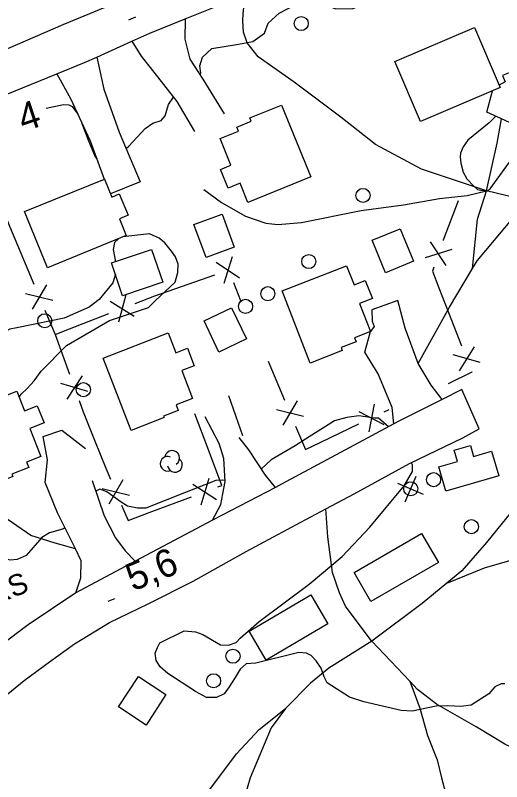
# Model space of a CAD drawing. Extents: x 362852 to 366875, y 5563573 to 5566479.
# Drawn here: x 363874.5 to 363943.6, y 5564816.7 to 5564925.6 of the extents above; entities that cross this region are included whole.
import ezdxf

# ---------------------------------------------------------------- set-up
doc = ezdxf.new("R2010")
doc.units = 0
for name, color, linetype in [('Niveau 19', 7, 'Continuous'), ('Niveau 2', 7, 'Continuous'), ('Niveau 21', 7, 'Continuous'), ('Niveau 22', 7, 'Continuous'), ('Niveau 3', 7, 'Continuous'), ('Niveau 31', 7, 'Continuous'), ('Niveau 36', 7, 'Continuous'), ('Niveau 37', 7, 'Continuous'), ('Niveau 44', 7, 'Continuous')]:
    doc.layers.add(name, color=color, linetype=linetype)

msp = doc.modelspace()

# ---------------------------------------------------------------- linework, layer by layer
at = {"layer": 'Niveau 19'}
for points in [[(363898.61, 5564925.08), (363898.55, 5564922.2), (363899.26, 5564919.35), (363901.09, 5564916.52), (363904.15, 5564911.57)], [(363952.27, 5564924.2), (363949.54, 5564920.62), (363945.08, 5564917.59), (363943.65, 5564917.03), (363944.03, 5564916.14), (363943.2, 5564915.67)], [(363891.04, 5564921.91), (363892.36, 5564919.76), (363893.64, 5564918.17), (363897.41, 5564913.32), (363899.92, 5564909.07)], [(363886.03, 5564919.65), (363887.04, 5564915.09), (363889.22, 5564908.99), (363892.22, 5564901.9), (363887.99, 5564900.23)], [(363880.36, 5564917.27), (363882.29, 5564913.77), (363885.12, 5564907.73), (363887.07, 5564902.29)], [(363956.14, 5564915.05), (363953.11, 5564914.84), (363951.63, 5564914.73), (363948.35, 5564913.76), (363945.91, 5564913.02), (363944.66, 5564910.37), (363943.52, 5564910.89), (363941.43, 5564911.83), (363942.25, 5564914.85)], [(363935.1, 5564870.99), (363933.55, 5564873), (363931.71, 5564876.09), (363929.84, 5564881.11), (363928.79, 5564885.05), (363925.1, 5564883.72), (363925.18, 5564882.12), (363925.43, 5564881.35), (363924.91, 5564880.63)], [(363928.23, 5564867.51), (363927.99, 5564869.84), (363926.01, 5564874.62), (363924.12, 5564877.69), (363924.91, 5564880.63)], [(363902.47, 5564853.86), (363903.65, 5564856.04), (363903.94, 5564857.6), (363904.27, 5564859.33), (363904.09, 5564862.59), (363903.45, 5564864.75), (363901.45, 5564868.53)], [(363883.09, 5564843.49), (363883.78, 5564845.66), (363883.85, 5564848.04), (363883, 5564849.75), (363880.45, 5564854.89), (363878.72, 5564859.2), (363879.05, 5564862.4), (363878.45, 5564865.73), (363881.08, 5564866.62), (363884.46, 5564864.04)], [(363911.42, 5564858.48), (363910, 5564860.24), (363907.62, 5564863.84), (363906.27, 5564865.58)], [(363885.38, 5564859.49), (363887.07, 5564854.46), (363888.68, 5564851.33), (363890.07, 5564849.48), (363891.48, 5564848)]]:
    msp.add_lwpolyline(points, dxfattribs=at)
at = {"layer": 'Niveau 2'}
for points in [[(363900.65, 5564917.2), (363900.82, 5564917.35), (363900.69, 5564918.42), (363901.07, 5564919.63), (363902.37, 5564920.86), (363906.17, 5564921.48), (363908.19, 5564921.87), (363909.88, 5564923.06), (363910.38, 5564924.45), (363911.96, 5564925.91), (363915.3, 5564927.65), (363916.71, 5564927.86), (363918.29, 5564927.19), (363919.95, 5564926.5), (363922.41, 5564926.57), (363924.73, 5564927.46), (363927.3, 5564928.95), (363931.28, 5564931.08), (363934.02, 5564932.77), (363935.99, 5564933.76), (363937.41, 5564933.78), (363939.68, 5564932.87)], [(363890.21, 5564906.64), (363890.59, 5564906.98), (363892.93, 5564909.5), (363893.99, 5564910.24), (363895.21, 5564910.62), (363895.75, 5564911.28), (363896.21, 5564912.9), (363896.92, 5564913.95)], [(363878.87, 5564912.39), (363881.32, 5564912.91), (363882.09, 5564912.86), (363882.56, 5564912.61), (363883.34, 5564911.53)], [(363942.73, 5564911.25), (363941.77, 5564910.32), (363938.74, 5564907.83), (363938.07, 5564906.87), (363937.69, 5564905.97), (363937.65, 5564905.45), (363937.77, 5564904.56), (363938.11, 5564903.27)], [(363883.88, 5564910.37), (363884.86, 5564907.75), (363885.8, 5564905.45), (363886.03, 5564905.2)], [(363938.11, 5564903.27), (363938.61, 5564902.35), (363939.49, 5564901.4), (363940.1, 5564900.84), (363940.58, 5564900.72), (363941.48, 5564900.66), (363941.94, 5564900.91), (363945.26, 5564905.58), (363945.71, 5564906.01), (363946.33, 5564906.33), (363947.2, 5564906.18), (363947.75, 5564905.6), (363948.25, 5564904.37), (363948.91, 5564902.89), (363949.8, 5564902.25), (363951.29, 5564901.8), (363955.09, 5564901.49), (363956.39, 5564900.59), (363956.99, 5564899.59), (363957.27, 5564898.27), (363959.82, 5564891.57), (363960.39, 5564889.6)], [(363875.03, 5564871.32), (363875.3, 5564871.73), (363876.14, 5564872.57), (363877.13, 5564873.66), (363878.13, 5564875.01), (363881.75, 5564878.67), (363887.83, 5564882.23), (363893.37, 5564884.06), (363894.4, 5564885.05), (363897.19, 5564887.68), (363897.57, 5564889.03), (363897.59, 5564890.22), (363897.23, 5564891.26), (363896.64, 5564892.08), (363895.72, 5564893.26), (363894.89, 5564893.92), (363893.52, 5564894.54), (363889.76, 5564894.08)], [(363889.13, 5564893.82), (363888.54, 5564893.31)], [(363888.54, 5564893.31), (363888.39, 5564892.31), (363888.68, 5564890.57)], [(363888.68, 5564888.79), (363888.34, 5564887.55), (363886.37, 5564885.19), (363884.95, 5564884.1), (363881.42, 5564882.53), (363874.69, 5564881.15), (363873.7, 5564880.99), (363872.97, 5564880.63), (363872.25, 5564879.65), (363869.62, 5564876.95), (363868.61, 5564876.53), (363867.67, 5564876.52), (363867.21, 5564876.64)], [(363927.5, 5564867.12), (363926.07, 5564868.33), (363925.51, 5564868.35), (363923.26, 5564868.67), (363921.56, 5564868.41), (363919.81, 5564867.95), (363915.71, 5564865.33), (363914.22, 5564864.41), (363910.81, 5564862.39), (363909.43, 5564861.11)], [(363881.5, 5564852.77), (363881.3, 5564852.6), (363880.19, 5564852.27), (363879.35, 5564852.05), (363878.26, 5564851.36), (363876, 5564848.81), (363874.74, 5564848.23), (363873.73, 5564848.13), (363869.31, 5564849.19), (363867.7, 5564850.08), (363866.61, 5564851.07), (363864.88, 5564854.23), (363863.96, 5564856.04), (363863.49, 5564857.34), (363863.03, 5564859.21), (363862.53, 5564861.81), (363863.09, 5564862.73), (363864.31, 5564863.1), (363867.59, 5564863.6)], [(363918.75, 5564830.72), (363918.35, 5564831.56), (363917.9, 5564832.81), (363917.23, 5564833.84), (363916.49, 5564834.6), (363915.84, 5564834.96), (363914.76, 5564835.01), (363908.65, 5564833.51), (363907.25, 5564833.43), (363906.39, 5564832.64), (363905.68, 5564831.48), (363904.86, 5564830.14), (363904.14, 5564829.16), (363903.04, 5564828.65), (363901.61, 5564828.63), (363900.08, 5564829.49), (363896.16, 5564832.07), (363895.04, 5564832.98), (363894.49, 5564833.88), (363894.36, 5564834.95), (363894.66, 5564835.75), (363895.02, 5564836.4), (363898.48, 5564838.13), (363900.05, 5564837.96), (363901.13, 5564837.59), (363903.6, 5564836.11), (363904.74, 5564836.08), (363905.83, 5564836.46), (363906.39, 5564837.07), (363909.1, 5564839.42), (363916.2, 5564844.76), (363920.89, 5564848.68), (363924.85, 5564852.86), (363929.69, 5564858.71), (363930.9, 5564860.77), (363930.9, 5564861.7), (363930.73, 5564861.99)], [(363904.26, 5564859.46), (363903.95, 5564859.51), (363902.97, 5564859.49), (363898.52, 5564857.72), (363893, 5564855.53), (363891.81, 5564855.54), (363890.39, 5564855.83), (363889.53, 5564856.41), (363887.49, 5564857.88), (363886.48, 5564858.22), (363885.89, 5564857.98)], [(363944.02, 5564830.6), (363943.47, 5564830.57), (363942.58, 5564830.14), (363941.74, 5564829.17), (363939.21, 5564827.57), (363937.75, 5564827.35), (363935.9, 5564827.46), (363934.24, 5564827.41), (363930.85, 5564826.7), (363929.26, 5564826.8), (363923.97, 5564828), (363921.96, 5564828.67), (363918.75, 5564830.72)]]:
    msp.add_lwpolyline(points, dxfattribs=at)
at = {"layer": 'Niveau 21'}
for points in [[(363870.87, 5564919.76), (363881.25, 5564924.26), (363891.6, 5564928.59), (363895.41, 5564930.17), (363900.53, 5564932.29), (363912.57, 5564937.29), (363928.35, 5564943.82), (363934.53, 5564946.23), (363937.14, 5564949.17), (363938.65, 5564952.79), (363938.85, 5564955.05), (363937.93, 5564957.54), (363937.26, 5564959.37), (363935.43, 5564963.45), (363931.81, 5564971.51), (363925.69, 5564985.72), (363924.02, 5564989.86), (363921.9, 5564995.12), (363920.66, 5564998.21), (363916.03, 5565008.95), (363915.68, 5565009.77), (363911.22, 5565019.68)], [(363873.15, 5564914.32), (363880.36, 5564917.27), (363884.3, 5564918.87), (363886.03, 5564919.65), (363891.04, 5564921.91), (363893.56, 5564923.05), (363898.61, 5564925.08), (363903.57, 5564927.08)], [(363870.3, 5564826.66), (363875.72, 5564831.07), (363879.31, 5564833.72), (363882.86, 5564836.28), (363887.87, 5564839.29), (363893.32, 5564841.94), (363899.72, 5564845.19), (363907.27, 5564849.39), (363915.03, 5564853.57), (363918.57, 5564855.45), (363922.59, 5564857.59), (363930.48, 5564861.87), (363938.02, 5564865.52), (363940.34, 5564866.84), (363939.31, 5564869.19), (363937.89, 5564872.39), (363935.1, 5564870.99), (363929.05, 5564867.96), (363928.23, 5564867.51), (363921.29, 5564863.78), (363912.28, 5564858.93), (363911.42, 5564858.48), (363902.47, 5564853.86), (363891.48, 5564848), (363883.09, 5564843.49), (363876.29, 5564838.96), (363872.44, 5564836.06)]]:
    msp.add_lwpolyline(points, dxfattribs=at)
at = {"layer": 'Niveau 22'}
for points in [[(363947.47, 5564899.17), (363941.42, 5564900.62), (363932.16, 5564903.74), (363925.62, 5564907.21), (363920.71, 5564911.11), (363914.08, 5564916.09), (363908.95, 5564919.67), (363907.4, 5564921.67), (363906.9, 5564923.21), (363906.81, 5564924.8), (363906.84, 5564925.81), (363907.11, 5564928.49)], [(363931.71, 5564876.09), (363936.13, 5564884.11), (363939.43, 5564889.62), (363940.09, 5564890.71), (363945.22, 5564896.83), (363947.47, 5564899.17), (363949.77, 5564901.55), (363951.47, 5564904.87), (363952.44, 5564907.39), (363952.94, 5564910.8), (363953.11, 5564914.84)], [(363939.43, 5564889.62), (363940.13, 5564896.61), (363941.42, 5564900.62), (363942.9, 5564907.42), (363943.52, 5564910.89)], [(363901.24, 5564900.82), (363903.74, 5564898.99), (363907.17, 5564897.05), (363910.06, 5564896.05), (363911.76, 5564895.87), (363915.14, 5564896.13), (363923.58, 5564897.83), (363929.59, 5564898.65), (363934.74, 5564899.55), (363938.67, 5564899.97), (363941.42, 5564900.62)], [(363883, 5564849.75), (363880.14, 5564850.58), (363876.7, 5564851.65), (363868.05, 5564857.58), (363865.4, 5564859.18), (363859.06, 5564860.51), (363849.16, 5564863.16), (363839.58, 5564865.1), (363829.88, 5564868.57), (363813.72, 5564873.06), (363805.19, 5564874.87), (363802.57, 5564876.23), (363801.32, 5564877.47), (363800.22, 5564878.64), (363797.88, 5564883.08)], [(363955.07, 5564870.77), (363951.94, 5564867.1), (363948.66, 5564861.82), (363946.28, 5564856.69), (363941.4, 5564850.64), (363937.88, 5564846.65), (363935.77, 5564844.9), (363932.27, 5564842.01), (363925.13, 5564836.65), (363919.01, 5564832.81), (363916.4, 5564830.69), (363912.85, 5564827.07), (363910.81, 5564824.31), (363907.84, 5564817.22), (363907.15, 5564814.95), (363904.68, 5564808.83), (363904, 5564802.89), (363903.68, 5564795.78)], [(363925.13, 5564836.65), (363925.03, 5564836.75), (363921.37, 5564841.61), (363920.53, 5564843.51), (363919.54, 5564846.42), (363918.87, 5564851.46), (363918.57, 5564855.45)], [(363935.77, 5564844.9), (363941.14, 5564847.05), (363947.64, 5564848.97), (363950.18, 5564849.33), (363953.77, 5564849.68), (363955.45, 5564849.89), (363958.04, 5564850.04), (363961.76, 5564850.06)], [(363995.27, 5564797), (363989.87, 5564795.79), (363982.96, 5564796.39), (363980.69, 5564797.39), (363978.61, 5564799.08), (363972.92, 5564804.79), (363969.64, 5564807.5), (363963.29, 5564812.38), (363961.25, 5564813.45), (363959.64, 5564814.31), (363958.81, 5564814.74), (363953.41, 5564817.56), (363944, 5564822), (363939.92, 5564824.49), (363934.28, 5564827.71), (363931.61, 5564829.78), (363930.51, 5564830.95), (363925.13, 5564836.65)], [(363930.51, 5564830.95), (363931.91, 5564827.11), (363933.02, 5564823.23), (363934.38, 5564819.8), (363935.01, 5564817.2), (363936.28, 5564812.42), (363937.25, 5564808.75), (363939.12, 5564802.29), (363939.63, 5564800.51)], [(363890.05, 5564800.28), (363896.53, 5564808.36), (363901.23, 5564814.41), (363905.91, 5564820.63), (363909.09, 5564824.1), (363912.85, 5564827.07)]]:
    msp.add_lwpolyline(points, dxfattribs=at)
at = {"layer": 'Niveau 3'}
for p, q in [((363890.61, 5564924.96), (363891.59, 5564925.35)), ((363887.66, 5564842.32), (363888.62, 5564842.71))]:
    msp.add_line(p, q, dxfattribs=at)
at = {"layer": 'Niveau 31'}
for points in [[(363943.35, 5564915.32), (363941.68, 5564914.61), (363932.04, 5564910.49), (363928.4, 5564919.02), (363939.72, 5564923.84), (363943.35, 5564915.32)], [(363916.44, 5564902.64), (363907.5, 5564898.99), (363906.39, 5564901.71), (363904.69, 5564901.01), (363903.6, 5564903.67), (363905.09, 5564904.28), (363903.55, 5564908.07), (363906.16, 5564909.13), (363905.92, 5564909.7), (363907.99, 5564910.54), (363907.8, 5564910.99), (363912.29, 5564912.82), (363916.44, 5564902.64)], [(363875.77, 5564897.68), (363887.13, 5564902.32), (363888.18, 5564899.76), (363889.24, 5564900.19), (363890.48, 5564897.16), (363889.26, 5564896.66), (363890.23, 5564894.27), (363879.03, 5564889.7), (363875.77, 5564897.68)], [(363903.85, 5564897.32), (363905.57, 5564892.64), (363901.57, 5564891.17), (363899.85, 5564895.84), (363903.85, 5564897.32)], [(363927.06, 5564888.99), (363925.17, 5564893.62), (363929.16, 5564895.25), (363931.05, 5564890.62), (363927.06, 5564888.99)], [(363893.82, 5564892.32), (363895.41, 5564887.66), (363889.72, 5564885.73), (363888.14, 5564890.39), (363893.82, 5564892.32)], [(363912.38, 5564886.44), (363921.53, 5564890), (363922.59, 5564887.27), (363924.19, 5564887.89), (363925.19, 5564885.34), (363923.35, 5564884.63), (363924.91, 5564880.63), (363922.67, 5564879.76), (363922.89, 5564879.19), (363920.75, 5564878.36), (363920.92, 5564877.94), (363916.37, 5564876.17), (363912.38, 5564886.44)], [(363905.17, 5564884.02), (363907.29, 5564879.59), (363903.4, 5564877.73), (363901.28, 5564882.16), (363905.17, 5564884.02)], [(363886.95, 5564876.88), (363896.17, 5564880.47), (363897.28, 5564877.63), (363898.93, 5564878.27), (363899.9, 5564875.78), (363898.12, 5564875.09), (363899.66, 5564871.14), (363897.31, 5564870.23), (363897.62, 5564869.42), (363895.53, 5564868.61), (363895.61, 5564868.41), (363890.95, 5564866.59), (363886.95, 5564876.88)], [(363865.62, 5564868.59), (363874.69, 5564872.17), (363875.79, 5564869.39), (363877.58, 5564870.1), (363878.55, 5564867.66), (363876.54, 5564866.87), (363878.12, 5564862.89), (363876.07, 5564862.08), (363876.38, 5564861.32), (363873.99, 5564860.38), (363874.13, 5564860.03), (363869.7, 5564858.27), (363865.62, 5564868.59)], [(363943.15, 5564860.14), (363935.64, 5564857.97), (363934.65, 5564861.4), (363937.29, 5564862.17), (363936.83, 5564863.77), (363939.12, 5564864.43), (363939.57, 5564862.9), (363942.13, 5564863.64), (363943.15, 5564860.14)], [(363934.57, 5564847.82), (363924.98, 5564842.29), (363922.6, 5564846.41), (363932.19, 5564851.94), (363934.57, 5564847.82)], [(363918.88, 5564839.12), (363910.1, 5564833.95), (363907.69, 5564838.04), (363916.47, 5564843.22), (363918.88, 5564839.12)], [(363895.87, 5564829.06), (363893.04, 5564824.72), (363889.11, 5564827.29), (363891.95, 5564831.63), (363895.87, 5564829.06)]]:
    msp.add_lwpolyline(points, dxfattribs=at)
at = {"layer": 'Niveau 36'}
for p, q in [((363929.86, 5564856.44), (363931.41, 5564860.11)), ((363932.47, 5564857.5), (363928.8, 5564859.05))]:
    msp.add_line(p, q, dxfattribs=at)
for centre in [(363915.08, 5564924.41), (363923.86, 5564899.98), (363916.16, 5564890.59), (363910.34, 5564886.02), (363907.18, 5564884.22), (363878.65, 5564882.17), (363884.14, 5564872.38), (363933.89, 5564859.59), (363930.64, 5564858.3), (363939.25, 5564852.91), (363905.39, 5564834.5), (363902.64, 5564831.01)]:
    msp.add_circle(centre, 1, dxfattribs=at)
at = {"layer": 'Niveau 37'}
for p, q in [((363874.78, 5564892.91), (363877.1, 5564887.38)), ((363935.69, 5564890.05), (363933.46, 5564893.37)), ((363936.48, 5564892.32), (363932.67, 5564891.1)), ((363905.28, 5564891.28), (363904.08, 5564887.47)), ((363903.02, 5564890.48), (363906.34, 5564888.26)), ((363897.14, 5564886.72), (363902.8, 5564888.72)), ((363878.88, 5564887.27), (363876.86, 5564883.81)), ((363905.46, 5564887.63), (363906.48, 5564885.04)), ((363879.81, 5564885.05), (363875.93, 5564886.02)), ((363890.18, 5564885.84), (363889.11, 5564881.98)), ((363887.94, 5564884.97), (363891.34, 5564882.85)), ((363935.66, 5564884.22), (363937.86, 5564878.63)), ((363882.19, 5564881.02), (363887.78, 5564883.19)), ((363880.12, 5564880.21), (363882.18, 5564874.57)), ((363939.63, 5564878.48), (363937.53, 5564875.07)), ((363910.37, 5564876.42), (363912.71, 5564870.9)), ((363940.51, 5564876.25), (363936.65, 5564877.31)), ((363883.95, 5564874.37), (363881.77, 5564871.02)), ((363884.77, 5564872.12), (363880.94, 5564873.28)), ((363906.78, 5564865.84), (363904.81, 5564871.51)), ((363914.49, 5564870.79), (363912.48, 5564867.33)), ((363925.46, 5564870.34), (363924.67, 5564866.41)), ((363901.9, 5564863.82), (363899.95, 5564868.94)), ((363915.43, 5564868.58), (363911.55, 5564869.54)), ((363923.29, 5564869.3), (363926.84, 5564867.45)), ((363926.87, 5564869.24), (363927.56, 5564869.57)), ((363917.85, 5564864.93), (363923.26, 5564867.52)), ((363889.76, 5564859.56), (363887.76, 5564856.1)), ((363899.7, 5564858.95), (363903.06, 5564856.79)), ((363901.94, 5564859.78), (363900.81, 5564855.95)), ((363890.7, 5564857.35), (363886.82, 5564858.31)), ((363893.88, 5564855.08), (363899.51, 5564857.17))]:
    msp.add_line(p, q, dxfattribs=at)
for points in [[(363872.55, 5564898.48), (363873.64, 5564895.61), (363874.78, 5564892.91)], [(363937.37, 5564899.2), (363935.25, 5564893.63), (363935.24, 5564893.59)], [(363933.92, 5564889.81), (363933.71, 5564889.21), (363934.62, 5564886.85), (363935.66, 5564884.22)], [(363891.51, 5564884.64), (363894.31, 5564885.73), (363897.14, 5564886.72)], [(363878.65, 5564883.69), (363880.12, 5564880.21), (363882.19, 5564881.02)], [(363939.32, 5564874.91), (363939.33, 5564874.89), (363935.97, 5564873.21)], [(363883.55, 5564870.82), (363884.13, 5564869.22), (363885.72, 5564865.22)], [(363914.27, 5564867.21), (363915.68, 5564863.9), (363917.85, 5564864.93)], [(363885.72, 5564865.22), (363887.32, 5564861.22), (363887.98, 5564859.67)], [(363903.26, 5564858.57), (363903.82, 5564858.78), (363901.9, 5564863.82)], [(363889.55, 5564855.99), (363890.48, 5564853.81), (363893.88, 5564855.08)]]:
    msp.add_lwpolyline(points, dxfattribs=at)
at = {"layer": 'Niveau 44'}
for centre, start, end in [((363896.75, 5564862.67), 304.3592, 171.8163), ((363896.11, 5564861.85), 66.2054, 291.894), ((363897.14, 5564861.7), 189.0269, 51.7112)]:
    msp.add_arc(centre, 1.05, start, end, dxfattribs=at)

# ---------------------------------------------------------------- texts
at = {"layer": 'Niveau 2'}
msp.add_text('4', height=3.93, rotation=18.3953, dxfattribs=at).set_placement((363875.62, 5564909))
at = {"layer": 'Niveau 3'}
msp.add_text('5,6  ', height=3.93, rotation=22.09, dxfattribs=at).set_placement((363891.17, 5564843.68))
at = {"layer": 'Niveau 31'}
msp.add_text('DE PROFESSEURS', height=3, rotation=22.2287, dxfattribs=at).set_placement((363842.36, 5564829.8))

doc.saveas('drawing.dxf')
